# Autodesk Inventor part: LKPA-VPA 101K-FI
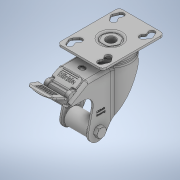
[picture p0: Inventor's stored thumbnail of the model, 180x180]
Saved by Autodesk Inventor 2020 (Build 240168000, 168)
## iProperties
Created: 1900-01
Part Number: LKPA-VPA 101K-FI
Material: Générique
Document SubType Name: Modeling
Designer: bruno
Density: 1 g/cm^3
Appearance: Par défaut
Author: bruno
Revision Number: ANYUNSPECIFIED
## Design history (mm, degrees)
feature "Base2"
feature "Base3"
feature "Base4"
node "Solide1"
node "Solide2"
node "Solide3"
node "Solide4"
